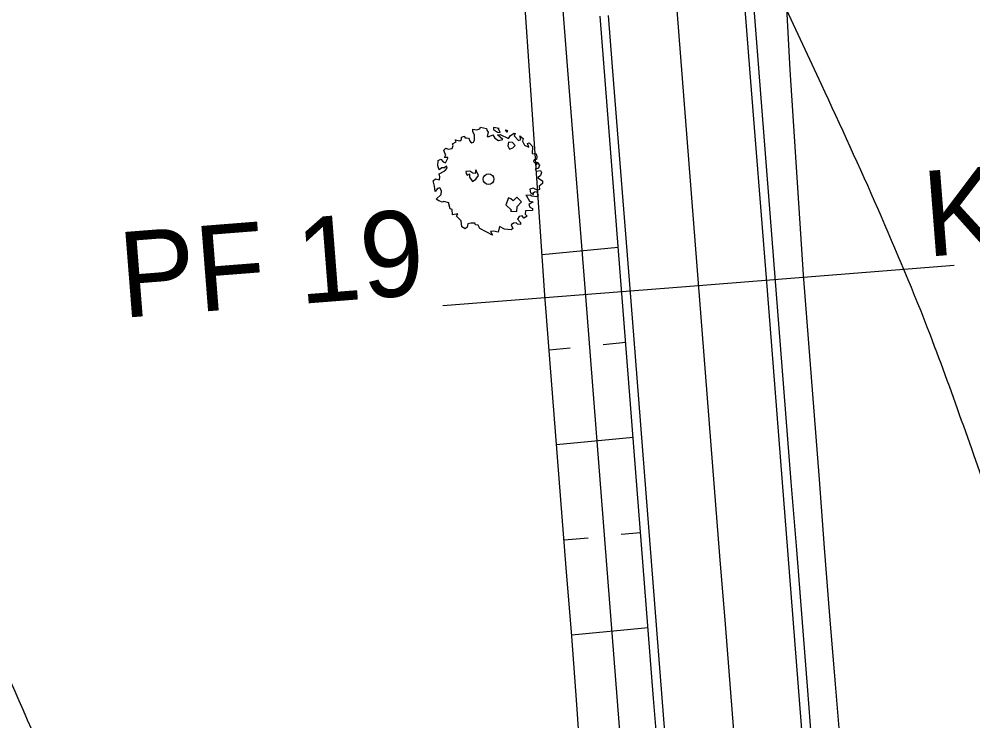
# Model space of a CAD drawing. Extents: x -477701 to -476785, y -1116511 to -1115314.
# Drawn here: x -477126.44 to -477098.55, y -1115673 to -1115652.49 of the extents above; entities that cross this region are included whole.
import ezdxf

# ---------------------------------------------------------------- set-up
doc = ezdxf.new("R2010")
doc.units = 0
for name, color, linetype in [('hrana_P', 7, 'Continuous'), ('hrana_R', 7, 'Continuous'), ('IP_RBK', 7, 'Continuous'), ('POLYGONY_SITUACE_PF', 7, 'Continuous'), ('POLYGONY_SITUACE_PF_POPISY', 7, 'Continuous'), ('svahování', 7, 'Continuous'), ('Vrstevnice_vedlejsi', 7, 'Continuous')]:
    doc.layers.add(name, color=color, linetype=linetype)

msp = doc.modelspace()

# ---------------------------------------------------------------- linework, layer by layer
at = {"layer": 'hrana_P'}
for points in [[(-477111.612, -1115652.572), (-477111.746, -1115650.577)], [(-477103.89, -1115653.972), (-477103.999, -1115651.974)], [(-477111.478, -1115654.568), (-477111.612, -1115652.572)], [(-477103.497, -1115659.959), (-477103.89, -1115653.972)], [(-477111.063, -1115660.554), (-477111.478, -1115654.568)], [(-477103.344, -1115661.954), (-477103.497, -1115659.959)], [(-477110.908, -1115662.548), (-477111.063, -1115660.554)], [(-477103.191, -1115663.948), (-477103.344, -1115661.954)], [(-477110.753, -1115664.542), (-477110.908, -1115662.548)], [(-477103.038, -1115665.942), (-477103.191, -1115663.948)], [(-477110.597, -1115666.536), (-477110.753, -1115664.542)], [(-477102.884, -1115667.936), (-477103.038, -1115665.942)], [(-477110.436, -1115668.529), (-477110.597, -1115666.536)], [(-477102.728, -1115669.93), (-477102.884, -1115667.936)], [(-477110.276, -1115670.523), (-477110.436, -1115668.529)], [(-477102.564, -1115671.923), (-477102.728, -1115669.93)], [(-477110.129, -1115672.517), (-477110.276, -1115670.523)], [(-477102.399, -1115673.916), (-477102.564, -1115671.923)], [(-477109.992, -1115674.513), (-477110.129, -1115672.517)]]:
    msp.add_lwpolyline(points, dxfattribs=at)
at = {"layer": 'hrana_R'}
for p, q in [((-477104.963, -1115652.05), (-477104.807, -1115654.044)), ((-477104.807, -1115654.044), (-477104.337, -1115660.025)), ((-477104.337, -1115660.025), (-477104.18, -1115662.019)), ((-477104.18, -1115662.019), (-477104.023, -1115664.013)), ((-477104.023, -1115664.013), (-477103.867, -1115666.007)), ((-477103.867, -1115666.007), (-477103.71, -1115668.001)), ((-477103.71, -1115668.001), (-477103.553, -1115669.995)), ((-477103.553, -1115669.995), (-477103.397, -1115671.988)), ((-477103.397, -1115671.988), (-477103.24, -1115673.982))]:
    msp.add_line(p, q, dxfattribs=at)
for points in [[(-477108.781, -1115674.417), (-477109.095, -1115670.429), (-477109.251, -1115668.435), (-477109.408, -1115666.441), (-477109.564, -1115664.448), (-477109.721, -1115662.455), (-477109.878, -1115660.461), (-477110.348, -1115654.478), (-477110.504, -1115652.484), (-477110.661, -1115650.491), (-477110.818, -1115648.498), (-477110.974, -1115646.503), (-477111.288, -1115642.515), (-477111.443, -1115640.541), (-477111.656, -1115638.702), (-477111.922, -1115636.759), (-477112.208, -1115634.813), (-477112.513, -1115632.87), (-477112.837, -1115630.93)], [(-477107.206, -1115652.226), (-477107.05, -1115654.22)], [(-477105.056, -1115654.063), (-477105.212, -1115652.069)], [(-477109.293, -1115654.396), (-477109.449, -1115652.402)], [(-477109.043, -1115654.377), (-477109.2, -1115652.383)], [(-477107.05, -1115654.22), (-477106.58, -1115660.202)], [(-477104.586, -1115660.045), (-477105.056, -1115654.063)], [(-477108.823, -1115660.378), (-477109.293, -1115654.396)], [(-477108.574, -1115660.358), (-477109.043, -1115654.377)], [(-477104.429, -1115662.039), (-477104.586, -1115660.045)], [(-477108.417, -1115662.352), (-477108.574, -1115660.358)], [(-477106.58, -1115660.202), (-477106.423, -1115662.195)], [(-477108.666, -1115662.372), (-477108.823, -1115660.378)], [(-477104.273, -1115664.033), (-477104.429, -1115662.039)], [(-477106.423, -1115662.195), (-477106.266, -1115664.189)], [(-477108.509, -1115664.365), (-477108.666, -1115662.372)], [(-477108.26, -1115664.346), (-477108.417, -1115662.352)], [(-477106.266, -1115664.189), (-477106.11, -1115666.183)], [(-477104.116, -1115666.026), (-477104.273, -1115664.033)], [(-477108.353, -1115666.359), (-477108.509, -1115664.365)], [(-477108.104, -1115666.34), (-477108.26, -1115664.346)], [(-477106.11, -1115666.183), (-477105.953, -1115668.177)], [(-477103.959, -1115668.02), (-477104.116, -1115666.026)], [(-477108.196, -1115668.353), (-477108.353, -1115666.359)], [(-477107.947, -1115668.334), (-477108.104, -1115666.34)], [(-477105.953, -1115668.177), (-477105.796, -1115670.171)], [(-477103.803, -1115670.014), (-477103.959, -1115668.02)], [(-477108.04, -1115670.347), (-477108.196, -1115668.353)], [(-477107.79, -1115670.327), (-477107.947, -1115668.334)], [(-477103.646, -1115672.008), (-477103.803, -1115670.014)], [(-477107.883, -1115672.341), (-477108.04, -1115670.347)], [(-477107.634, -1115672.321), (-477107.79, -1115670.327)], [(-477105.796, -1115670.171), (-477105.64, -1115672.165)], [(-477103.489, -1115674.002), (-477103.646, -1115672.008)], [(-477107.726, -1115674.335), (-477107.883, -1115672.341)], [(-477107.477, -1115674.315), (-477107.634, -1115672.321)], [(-477105.64, -1115672.165), (-477105.483, -1115674.159)]]:
    msp.add_lwpolyline(points, dxfattribs=at)
at = {"layer": 'IP_RBK'}
for points in [[(-477111.794, -1115655.903), (-477111.699, -1115655.975), (-477111.721, -1115656.058), (-477111.662, -1115656.171), (-477111.528, -1115656.232), (-477111.571, -1115656.123), (-477111.52, -1115656.108), (-477111.405, -1115656.232), (-477111.428, -1115656.224), (-477111.437, -1115656.414), (-477111.32, -1115656.427), (-477111.295, -1115656.51), (-477111.31, -1115656.586), (-477111.376, -1115656.602), (-477111.395, -1115656.647), (-477111.298, -1115656.745), (-477111.285, -1115656.666), (-477111.225, -1115656.757), (-477111.248, -1115656.843), (-477111.347, -1115656.875), (-477111.316, -1115656.936), (-477111.193, -1115656.909), (-477111.158, -1115656.969), (-477111.195, -1115657.056), (-477111.271, -1115657.129), (-477111.135, -1115657.211), (-477111.137, -1115657.29), (-477111.229, -1115657.373), (-477111.219, -1115657.472), (-477111.288, -1115657.487), (-477111.41, -1115657.429), (-477111.503, -1115657.46), (-477111.487, -1115657.562), (-477111.4, -1115657.616), (-477111.407, -1115657.562), (-477111.363, -1115657.538), (-477111.306, -1115657.526), (-477111.259, -1115657.624), (-477111.301, -1115657.681), (-477111.445, -1115657.662), (-477111.495, -1115657.63), (-477111.618, -1115657.647), (-477111.605, -1115657.652), (-477111.515, -1115657.812), (-477111.41, -1115657.825), (-477111.531, -1115657.904), (-477111.507, -1115657.982), (-477111.421, -1115658.018), (-477111.423, -1115658.08), (-477111.632, -1115658.091), (-477111.636, -1115658.193), (-477111.578, -1115658.243), (-477111.683, -1115658.303), (-477111.727, -1115658.238), (-477111.815, -1115658.259), (-477111.867, -1115658.338), (-477111.775, -1115658.432), (-477111.775, -1115658.489), (-477111.861, -1115658.476), (-477111.906, -1115658.446), (-477111.984, -1115658.449), (-477112.053, -1115658.503), (-477112.004, -1115658.605), (-477112.045, -1115658.643), (-477112.244, -1115658.622), (-477112.391, -1115658.544), (-477112.429, -1115658.717), (-477112.563, -1115658.682), (-477112.657, -1115658.693), (-477112.597, -1115658.801), (-477112.967, -1115658.609), (-477113.012, -1115658.505), (-477113.095, -1115658.501), (-477113.112, -1115658.453), (-477113.228, -1115658.451), (-477113.316, -1115658.468), (-477113.335, -1115658.568), (-477113.391, -1115658.613), (-477113.491, -1115658.562), (-477113.511, -1115658.38), (-477113.645, -1115658.251), (-477113.606, -1115658.179), (-477113.763, -1115658.207), (-477113.773, -1115658.05), (-477113.83, -1115658.033), (-477113.871, -1115657.889), (-477113.87, -1115657.855), (-477114.018, -1115657.815), (-477114.061, -1115657.839), (-477114.162, -1115657.802), (-477114.243, -1115657.75), (-477114.092, -1115657.616), (-477114.088, -1115657.509), (-477114.131, -1115657.417), (-477114.201, -1115657.44), (-477114.27, -1115657.521), (-477114.289, -1115657.369), (-477114.327, -1115657.21), (-477114.265, -1115657.155), (-477114.144, -1115657.181), (-477114.132, -1115657.101), (-477114.153, -1115657.005), (-477113.987, -1115656.919), (-477113.924, -1115656.846), (-477113.936, -1115656.786), (-477113.998, -1115656.835), (-477114.072, -1115656.835), (-477114.158, -1115656.889), (-477114.193, -1115656.777), (-477114.183, -1115656.615), (-477114.106, -1115656.584), (-477114.041, -1115656.661), (-477113.971, -1115656.687), (-477113.905, -1115656.552), (-477113.898, -1115656.529), (-477113.998, -1115656.528), (-477113.96, -1115656.452), (-477113.989, -1115656.405), (-477114.017, -1115656.322), (-477113.959, -1115656.256), (-477113.893, -1115656.284), (-477113.778, -1115656.273), (-477113.749, -1115656.185), (-477113.761, -1115656.13), (-477113.66, -1115656.073), (-477113.686, -1115656.013), (-477113.554, -1115656.041), (-477113.496, -1115656.008), (-477113.499, -1115655.941), (-477113.412, -1115655.912), (-477113.403, -1115655.957), (-477113.351, -1115655.953), (-477113.295, -1115655.969), (-477113.273, -1115655.994), (-477113.263, -1115656.037), (-477113.236, -1115656.075), (-477113.201, -1115656.102), (-477113.148, -1115656.086), (-477113.125, -1115656.023), (-477113.124, -1115655.881), (-477113.171, -1115655.772), (-477113.166, -1115655.705), (-477113.049, -1115655.725), (-477112.965, -1115655.696), (-477112.945, -1115655.646), (-477112.771, -1115655.685), (-477112.756, -1115655.729), (-477112.717, -1115655.79), (-477112.752, -1115655.916), (-477112.689, -1115655.921), (-477112.589, -1115655.865), (-477112.526, -1115655.967), (-477112.42, -1115656.037), (-477112.29, -1115656.009), (-477112.453, -1115655.866), (-477112.366, -1115655.859), (-477112.124, -1115655.972), (-477112.072, -1115655.886), (-477111.963, -1115655.822), (-477111.934, -1115655.835), (-477111.965, -1115655.901), (-477111.832, -1115656.032), (-477111.77, -1115656.004)], [(-477112.562, -1115655.716), (-477112.449, -1115655.788), (-477112.375, -1115655.797), (-477112.422, -1115655.698), (-477112.402, -1115655.683), (-477112.561, -1115655.66)], [(-477112.226, -1115655.737), (-477112.177, -1115655.788), (-477112.146, -1115655.763), (-477112.162, -1115655.741)], [(-477112.125, -1115656.088), (-477112.143, -1115656.188), (-477112.093, -1115656.284), (-477112.004, -1115656.251), (-477111.934, -1115656.185), (-477112.007, -1115656.097)], [(-477113.264, -1115657.011), (-477113.264, -1115657.103), (-477113.181, -1115657.232), (-477113.084, -1115657.17), (-477113.003, -1115657.058), (-477113.081, -1115656.891), (-477113.101, -1115657.004), (-477113.166, -1115656.993), (-477113.228, -1115656.948), (-477113.255, -1115656.928), (-477113.375, -1115656.943), (-477113.368, -1115657.003), (-477113.335, -1115657.052), (-477113.289, -1115657.033)], [(-477112.13, -1115657.706), (-477112.203, -1115657.917), (-477112.036, -1115658.071), (-477112.067, -1115658.105), (-477111.881, -1115658.11), (-477111.878, -1115657.969), (-477111.744, -1115657.827), (-477111.886, -1115657.693), (-477111.988, -1115657.801), (-477112.055, -1115657.738)]]:
    msp.add_lwpolyline(points, close=True, dxfattribs=at)
msp.add_circle((-477112.711, -1115657.165), 0.158, dxfattribs=at)
at = {"layer": 'POLYGONY_SITUACE_PF'}
msp.add_lwpolyline([(-477114.051, -1115660.857), (-477106.574, -1115660.269), (-477099.097, -1115659.682)], dxfattribs=at)
at = {"layer": 'svahování'}
for points in [[(-477108.918, -1115659.164), (-477111.144, -1115659.375)], [(-477108.918, -1115659.164), (-477111.144, -1115659.375)], [(-477108.918, -1115659.164), (-477111.144, -1115659.375)], [(-477108.7, -1115661.942), (-477109.363, -1115662.005)], [(-477108.7, -1115661.942), (-477109.363, -1115662.005)], [(-477108.7, -1115661.942), (-477109.363, -1115662.005)], [(-477110.938, -1115662.154), (-477110.324, -1115662.096)], [(-477110.938, -1115662.154), (-477110.324, -1115662.096)], [(-477110.938, -1115662.154), (-477110.324, -1115662.096)], [(-477108.481, -1115664.72), (-477110.722, -1115664.933)], [(-477108.481, -1115664.72), (-477110.722, -1115664.933)], [(-477108.481, -1115664.72), (-477110.722, -1115664.933)], [(-477108.263, -1115667.499), (-477108.837, -1115667.553)], [(-477108.263, -1115667.499), (-477108.837, -1115667.553)], [(-477108.263, -1115667.499), (-477108.837, -1115667.553)], [(-477110.502, -1115667.711), (-477109.799, -1115667.644)], [(-477110.502, -1115667.711), (-477109.799, -1115667.644)], [(-477110.502, -1115667.711), (-477109.799, -1115667.644)], [(-477108.045, -1115670.277), (-477110.278, -1115670.488)], [(-477108.045, -1115670.277), (-477110.278, -1115670.488)], [(-477108.045, -1115670.277), (-477110.278, -1115670.488)]]:
    msp.add_lwpolyline(points, dxfattribs=at)
at = {"layer": 'Vrstevnice_vedlejsi'}
for points in [[(-477255.435, -1115434.86), (-477253.737, -1115436.866), (-477249.056, -1115442.643), (-477244.281, -1115448.922), (-477240.745, -1115453.867), (-477238.449, -1115457.48), (-477237.392, -1115459.76), (-477236.511, -1115461.808), (-477235.807, -1115463.625), (-477235.279, -1115465.21), (-477233.755, -1115470.183), (-477231.237, -1115478.544), (-477227.724, -1115490.292), (-477222.637, -1115501.303), (-477215.976, -1115511.578), (-477207.741, -1115521.116), (-477201.74, -1115528.174), (-477197.974, -1115532.752), (-477196.443, -1115534.851), (-477195.455, -1115536.349), (-477195.012, -1115537.247), (-477195.112, -1115537.544), (-477194.515, -1115538.208), (-477193.22, -1115539.24), (-477191.228, -1115540.64), (-477186.597, -1115544.487), (-477179.326, -1115550.78), (-477169.416, -1115559.52), (-477161.161, -1115566.877), (-477154.562, -1115572.853), (-477149.618, -1115577.447), (-477145.626, -1115581.448), (-477142.586, -1115584.858), (-477140.499, -1115587.676), (-477137.77, -1115591.397), (-477134.4, -1115596.021), (-477130.387, -1115601.547), (-477126.925, -1115606.82), (-477124.013, -1115611.841), (-477121.651, -1115616.609), (-477120.074, -1115619.788), (-477119.28, -1115621.378), (-477119.27, -1115621.378), (-477119.257, -1115621.401), (-477119.241, -1115621.446), (-477119.222, -1115621.515), (-477119.202, -1115621.585), (-477119.181, -1115621.658), (-477119.16, -1115621.733), (-477119.135, -1115621.808), (-477119.105, -1115621.885), (-477119.072, -1115621.962), (-477119.032, -1115622.064), (-477118.986, -1115622.189), (-477118.934, -1115622.339), (-477116.991, -1115626.204), (-477113.158, -1115633.786), (-477107.434, -1115645.084), (-477102.982, -1115654.393), (-477099.802, -1115661.714), (-477097.892, -1115667.048), (-477096.088, -1115672.077), (-477094.388, -1115676.803), (-477092.792, -1115681.225), (-477091.708, -1115684.393), (-477091.134, -1115686.307), (-477091.072, -1115686.967), (-477091.025, -1115687.641), (-477090.994, -1115688.331), (-477090.979, -1115689.037), (-477091.009, -1115689.591), (-477091.085, -1115689.993), (-477091.207, -1115690.245), (-477091.411, -1115690.833), (-477091.696, -1115691.757), (-477092.064, -1115693.018), (-477092.517, -1115694.69), (-477093.055, -1115696.773), (-477093.679, -1115699.266), (-477094.113, -1115701.029), (-477094.357, -1115702.059), (-477094.411, -1115702.359), (-477094.445, -1115702.639), (-477094.461, -1115702.898)], [(-477007.138, -1115953.579), (-477005.826, -1115949.576), (-477005.144, -1115946.145), (-477005.093, -1115943.286), (-477005.673, -1115940.999), (-477007.165, -1115938.437), (-477009.569, -1115935.601), (-477012.885, -1115932.489), (-477014.789, -1115928.003), (-477015.281, -1115922.144), (-477014.36, -1115914.911), (-477013.331, -1115909.535), (-477012.194, -1115906.016), (-477010.948, -1115904.355), (-477009.951, -1115900.899), (-477009.205, -1115895.651), (-477008.708, -1115888.609), (-477008.182, -1115882.918), (-477007.627, -1115878.577), (-477007.043, -1115875.588), (-477006.707, -1115873.561), (-477006.621, -1115872.496), (-477006.782, -1115872.394), (-477007.841, -1115871.139), (-477009.796, -1115868.729), (-477012.648, -1115865.165), (-477016.214, -1115861.165), (-477020.492, -1115856.728), (-477025.484, -1115851.855), (-477028.981, -1115848.432), (-477030.984, -1115846.46), (-477031.493, -1115845.939), (-477032.666, -1115844.42), (-477034.503, -1115841.902), (-477037.004, -1115838.386), (-477039.928, -1115834.617), (-477043.274, -1115830.594), (-477047.042, -1115826.317), (-477050.823, -1115820.94), (-477054.619, -1115814.463), (-477058.428, -1115806.886), (-477061.996, -1115799.916), (-477065.321, -1115793.552), (-477068.406, -1115787.796), (-477071.352, -1115782.346), (-477074.162, -1115777.2), (-477076.834, -1115772.361), (-477079.753, -1115767.439), (-477082.919, -1115762.435), (-477086.331, -1115757.348), (-477089.206, -1115752.822), (-477091.543, -1115748.855), (-477093.343, -1115745.447), (-477095.522, -1115741.838), (-477098.081, -1115738.025), (-477101.02, -1115734.011), (-477103.278, -1115730.75), (-477104.853, -1115728.243), (-477105.746, -1115726.49), (-477107.339, -1115722.954), (-477109.63, -1115717.636), (-477112.62, -1115710.535), (-477114.608, -1115705.71), (-477115.592, -1115703.16), (-477115.574, -1115702.886), (-477115.555, -1115702.594), (-477115.535, -1115702.283), (-477115.513, -1115701.954), (-477115.52, -1115701.651), (-477115.554, -1115701.375), (-477115.617, -1115701.126), (-477116.084, -1115699.641), (-477116.955, -1115696.919), (-477118.231, -1115692.961), (-477120.339, -1115687.326), (-477123.282, -1115680.015), (-477127.058, -1115671.028), (-477132.156, -1115661.196), (-477138.577, -1115650.521), (-477146.32, -1115639.002), (-477151.901, -1115630.718), (-477155.32, -1115625.669), (-477156.577, -1115623.854), (-477157.449, -1115622.576), (-477157.936, -1115621.834), (-477158.038, -1115621.629), (-477158.258, -1115621.282), (-477158.595, -1115620.796), (-477159.051, -1115620.169), (-477162.695, -1115615.586), (-477169.529, -1115607.047), (-477179.552, -1115594.552), (-477187.337, -1115585.256), (-477192.883, -1115579.159), (-477196.191, -1115576.261), (-477200.636, -1115573.088), (-477206.218, -1115569.639)], [(-477056.772, -1115848.927), (-477068.139, -1115835.813), (-477075.756, -1115827.036), (-477079.622, -1115822.596), (-477079.737, -1115822.491), (-477079.838, -1115822.383), (-477079.923, -1115822.271), (-477079.993, -1115822.156), (-477081.592, -1115819.248), (-477084.72, -1115813.549), (-477089.376, -1115805.058), (-477093.467, -1115797.78), (-477096.993, -1115791.716), (-477099.953, -1115786.865), (-477102.668, -1115782.526), (-477105.137, -1115778.7), (-477107.36, -1115775.386), (-477109.946, -1115771.088), (-477112.893, -1115765.806), (-477116.202, -1115759.541), (-477119.472, -1115754.116), (-477122.702, -1115749.531), (-477125.893, -1115745.785), (-477129.063, -1115741.182), (-477132.212, -1115735.72), (-477135.339, -1115729.4), (-477138.871, -1115722.849), (-477142.808, -1115716.067), (-477147.15, -1115709.053), (-477150.935, -1115702.542), (-477154.163, -1115696.532), (-477156.834, -1115691.024), (-477159.669, -1115685.797), (-477162.666, -1115680.85), (-477165.825, -1115676.184), (-477168.762, -1115672.021), (-477171.477, -1115668.359), (-477173.969, -1115665.2), (-477176.835, -1115661.738), (-477180.076, -1115657.973), (-477183.691, -1115653.906), (-477187.456, -1115649.307), (-477191.372, -1115644.176), (-477195.439, -1115638.512), (-477199.76, -1115633.535), (-477204.333, -1115629.245), (-477209.161, -1115625.643), (-477214.066, -1115622.094), (-477219.05, -1115618.599), (-477224.112, -1115615.157), (-477228.635, -1115611.661), (-477232.618, -1115608.111), (-477233.487, -1115607.232), (-477234.302, -1115606.307), (-477235.137, -1115605.382), (-477236.062, -1115604.507), (-477240.936, -1115602.586), (-477247.24, -1115602.349), (-477249.172, -1115602.669), (-477251.098, -1115603.084), (-477253.028, -1115603.493), (-477254.975, -1115603.796), (-477261.993, -1115604.195), (-477268.296, -1115603.546), (-477269.716, -1115603.191), (-477271.101, -1115602.711), (-477272.48, -1115602.224), (-477273.884, -1115601.849), (-477279.02, -1115601.743), (-477283.705, -1115603.227), (-477287.938, -1115606.301), (-477291.907, -1115609.757), (-477295.612, -1115613.596), (-477299.053, -1115617.818), (-477302.381, -1115621.488), (-477305.597, -1115624.607), (-477308.702, -1115627.173), (-477311.627, -1115630.795), (-477314.373, -1115635.471), (-477316.939, -1115641.202), (-477319.217, -1115646.135), (-477321.206, -1115650.269), (-477322.906, -1115653.604), (-477324.042, -1115656.397), (-477324.613, -1115658.648), (-477324.619, -1115660.357), (-477325.689, -1115664.318), (-477327.358, -1115669.242)]]:
    msp.add_spline(points, degree=3, dxfattribs=at)

# ---------------------------------------------------------------- texts
at = {"layer": 'POLYGONY_SITUACE_PF_POPISY'}
for s, p in [('KM=0.530', (-477099.897, -1115659.434)), ('PF 19', (-477123.407, -1115661.221))]:
    msp.add_text(s, height=2.5, rotation=4.492, dxfattribs=at).set_placement(p)

doc.saveas('drawing.dxf')
